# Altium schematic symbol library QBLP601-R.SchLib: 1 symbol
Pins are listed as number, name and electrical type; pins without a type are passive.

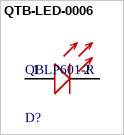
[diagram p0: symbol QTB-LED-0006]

## QTB-LED-0006
designator D?, comment QBLP601-R
LED RED CLEAR 0603 SMD; Manufacturer: QT Brightek (QTB); Lens Size: 0.8mm; Luminous Intensity: 100mcd; Test Current: 20mA; Lens Color: Colorless; Lens Style: Flat; Forward Voltage: 2.0V; Wavelength - Dominant: 625nm
footprint QBLP601-R-MFG
pins: 1 ANODE (+), 2 CATHODE (-)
